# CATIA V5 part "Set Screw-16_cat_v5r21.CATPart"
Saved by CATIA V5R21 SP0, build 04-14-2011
Part number: Set Screw-16
Bounding box of the stored display mesh (mm): x -5.916 to 5.916, y -5.998 to 5.998, z -1.5 to 20.171
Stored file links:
  D:\CATIA V5R21 E-RESOURCES\CATIA-V5R21\catia-v5r21-Tut\c13-catia-v5r21-tut\c13-catia-v5r21-tut02\Bench Vice\Set Screw-16_cat_v5r21.CATPart
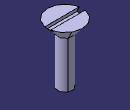
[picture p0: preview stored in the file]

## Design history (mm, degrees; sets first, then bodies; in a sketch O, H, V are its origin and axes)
Body1 (main body)
  Sketch1 on yz-plane, origin (0, 0, 0), H (0, 1, 0), V (0, 0, 1)
    point P1 (0, -1.5)
    line L1 (0, -1.5) -> (2.5, 0)
    point P2 (2.5, 0)
    line L2 (2.5, 0) -> (2.5, 16)
    line L3 (2.5, 16) -> (6, 20.1711)
    point P4 (6, 20.1711)
    line L4 (6, 20.1711) -> (0, 20.1711)
    point P5 (0, 20.1711)
    line L5 (0, 20.1711) -> (0, -1.5)
    length L2 = 16
    distance L2 L5 = 2.5
    distance H P1 = 1.5
    distance P4 L5 = 6
    angle L3 L5 = 40
    coincidence: P1 V, P2 H, P5 V
    vertical: L2 V, L5 V
    horizontal: L4 H
  Shaft1: profile Sketch1, axis edge of Sketch1, angle 360
  Sketch2 on yz-plane, origin (0, 0, 0), H (0, 1, 0), V (0, 0, 1)
    line L1 (-1, 20.1711) -> (1, 20.1711)
    line L2 (1, 20.1711) -> (1, 19.1711)
    line L3 (1, 19.1711) -> (-1, 19.1711)
    line L4 (-1, 19.1711) -> (-1, 20.1711)
    reference projected line E1 (-6, 20.1711) -> (6, 20.1711) from edge of Shaft1
    distance V L2 = 1
    length L1 = 2
    length L2 = 1
    horizontal: L1 H, L3 H
    vertical: L2 V, L4 V
    coincidence: L1 E1
  Pocket1: profile Sketch2, direction (-1, 0, 0), length 16, mirrored extent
